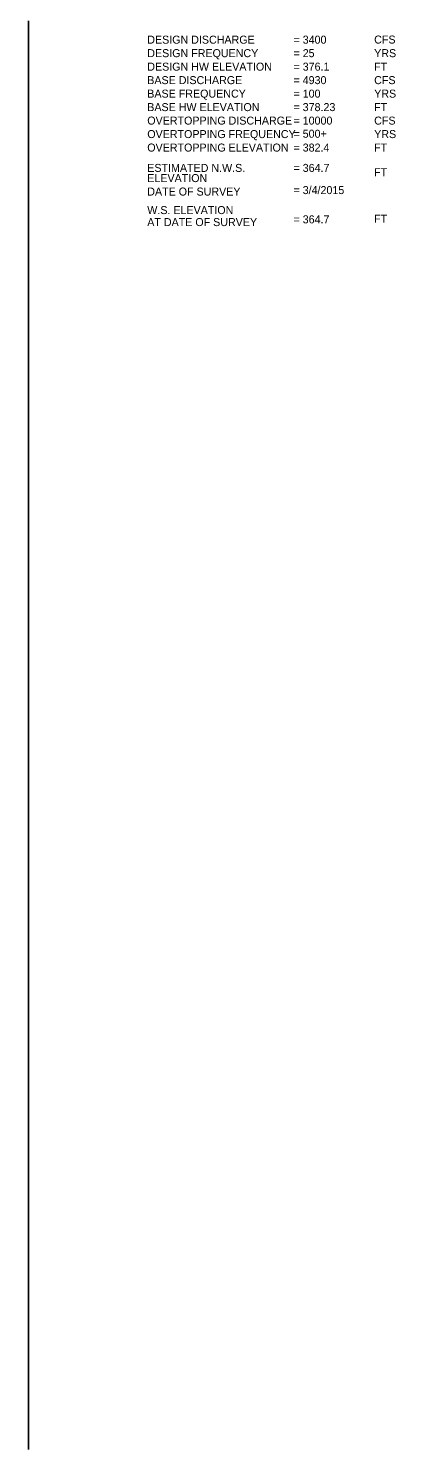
# Model space of a CAD drawing. Extents: x 2099451 to 2100919, y 990328 to 992828.
# Drawn here: x 2099512 to 2099834, y 990328 to 991572 of the extents above; entities that cross this region are included whole.
import ezdxf

# ---------------------------------------------------------------- set-up
doc = ezdxf.new("R2010")
doc.units = 0
doc.layers.add('Exist Profile Cell', color=7, linetype='Continuous')
doc.layers.add('Prop PFL Culvert Hydraulic Data Label CELL', color=7, linetype='Continuous')

msp = doc.modelspace()

# ---------------------------------------------------------------- linework, layer by layer
at = {"layer": 'Exist Profile Cell'}
msp.add_line((2099512.1, 991578.3), (2099512.1, 990328.3), dxfattribs=at)

# ---------------------------------------------------------------- texts
at = {"layer": 'Prop PFL Culvert Hydraulic Data Label CELL'}
for s, p in [('DESIGN DISCHARGE', (2099616.3, 991558.4)), ('= 3400', (2099744.4, 991558.4)), ('CFS', (2099815.1, 991558.5)), ('DESIGN FREQUENCY', (2099616.3, 991546.6)), ('= 25', (2099744.4, 991546.6)), ('YRS', (2099815.1, 991546.6)), ('DESIGN HW ELEVATION', (2099616.3, 991534.8)), ('= 376.1', (2099744.4, 991534.8)), ('FT', (2099815.1, 991534.8)), ('BASE DISCHARGE', (2099616.3, 991523)), ('BASE FREQUENCY', (2099616.3, 991511.2)), ('= 4930', (2099744.4, 991523)), ('= 100', (2099744.4, 991511.2)), ('YRS', (2099815.1, 991511.2)), ('CFS', (2099815.1, 991523)), ('BASE HW ELEVATION', (2099616.3, 991499.4)), ('= 378.23', (2099744.4, 991499.4)), ('FT', (2099815.1, 991499.4)), ('OVERTOPPING DISCHARGE', (2099616.3, 991487.6)), ('= 10000', (2099744.4, 991487.6)), ('CFS', (2099815.1, 991487.6)), ('OVERTOPPING FREQUENCY', (2099616.3, 991475.8)), ('= 500+', (2099744.4, 991476.1)), ('YRS', (2099815.1, 991475.8)), ('OVERTOPPING ELEVATION', (2099616.3, 991464)), ('= 382.4', (2099744.4, 991464)), ('FT', (2099815.1, 991464)), ('ESTIMATED N.W.S.', (2099616.3, 991446.2)), ('ELEVATION', (2099616.3, 991437.3)), ('= 364.7', (2099744.4, 991446.2)), ('FT', (2099815.1, 991442.4)), ('DATE OF SURVEY', (2099616.3, 991425.5)), ('= 3/4/2015', (2099744.4, 991426.8)), ('W.S. ELEVATION', (2099616.3, 991409.3)), ('AT DATE OF SURVEY', (2099616.3, 991398.8)), ('= 364.7', (2099744.4, 991401.2)), ('FT', (2099815.1, 991401.8))]:
    msp.add_text(s, height=7, dxfattribs=at).set_placement(p)

doc.saveas('drawing.dxf')
